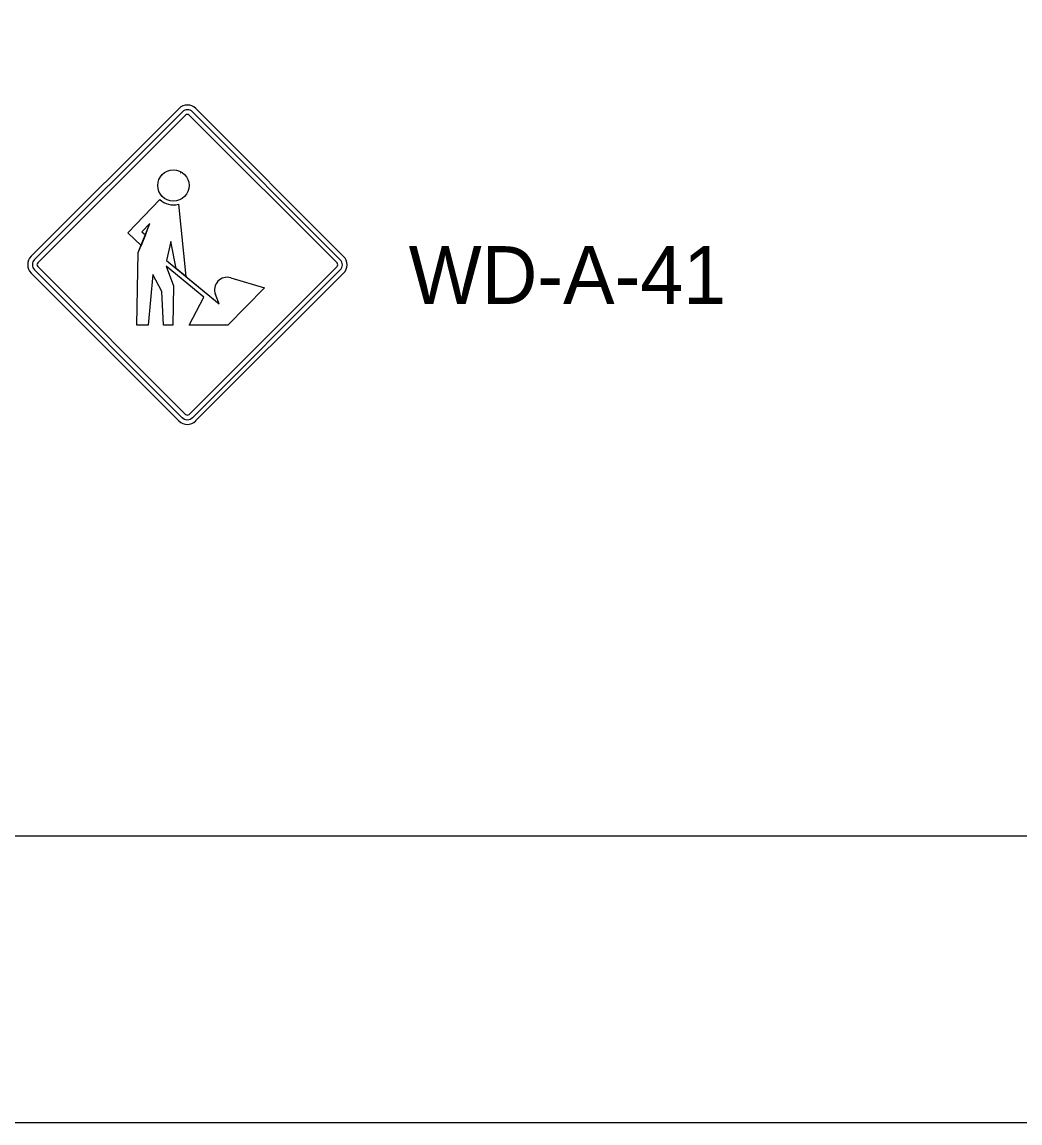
# Model space of a CAD drawing. Extents: x 2195 to 2411, y 202 to 481.
# Drawn here: x 2299.55 to 2337.18, y 201.88 to 243.38 of the extents above; entities that cross this region are included whole.
import ezdxf

# ---------------------------------------------------------------- set-up
doc = ezdxf.new("R2010")
doc.units = 0
for name, color, linetype in [('Level 1', 7, 'Continuous'), ('Level 10', 7, 'Continuous'), ('Level 60', 7, 'Continuous')]:
    doc.layers.add(name, color=color, linetype=linetype)

msp = doc.modelspace()

# ---------------------------------------------------------------- linework, layer by layer
at = {"layer": 'Level 1'}
for p, q in [((2305.47, 240.119), (2299.892, 234.546)), ((2305.594, 239.994), (2300.016, 234.422)), ((2305.718, 239.87), (2300.14, 234.299)), ((2311.427, 234.296), (2305.852, 239.87)), ((2311.55, 234.42), (2305.976, 239.993)), ((2311.674, 234.542), (2306.1, 240.117)), ((2305.525, 237.676), (2305.51, 237.676)), ((2300.016, 234.04), (2305.59, 228.465)), ((2300.14, 234.164), (2305.715, 228.59)), ((2305.849, 228.59), (2311.426, 234.161)), ((2305.973, 228.465), (2311.55, 234.036)), ((2299.892, 233.916), (2305.466, 228.341)), ((2306.096, 228.341), (2311.674, 233.912))]:
    msp.add_line(p, q, dxfattribs=at)
for points in [[(2304.063, 235.469), (2304.198, 235.356), (2304.037, 234.953), (2303.532, 235.431), (2304.748, 236.686)], [(2304.063, 235.469), (2304.198, 235.356), (2304.037, 234.953), (2303.532, 235.431), (2304.748, 236.686)], [(2304.48, 233.86), (2304.302, 231.957), (2303.875, 231.957), (2303.933, 234.69), (2304.038, 234.953), (2303.532, 235.431), (2304.748, 236.686)], [(2305.445, 236.508), (2305.727, 233.788), (2305.364, 234.087), (2305.158, 235.1), (2304.99, 234.395), (2306.976, 232.757), (2306.839, 233.111)], [(2305.445, 236.508), (2305.727, 233.788), (2305.364, 234.087), (2305.158, 235.1), (2304.99, 234.395), (2306.976, 232.757), (2306.839, 233.111)], [(2305.445, 236.508), (2305.727, 233.786), (2306.976, 232.757), (2306.839, 233.111)], [(2307.418, 233.738), (2308.698, 233.356), (2307.314, 231.957), (2305.857, 231.957), (2306.403, 233.012), (2304.989, 234.17), (2305.266, 233.432), (2305.23, 231.957), (2304.883, 231.957), (2304.82, 233.217), (2304.48, 233.86), (2304.302, 231.957), (2303.875, 231.957), (2303.933, 234.69), (2304.372, 235.786), (2304.063, 235.469)], [(2307.418, 233.738), (2308.698, 233.356), (2307.314, 231.957), (2305.857, 231.957), (2306.403, 233.012), (2304.989, 234.17), (2305.266, 233.432), (2305.23, 231.957), (2304.883, 231.957), (2304.82, 233.217), (2304.48, 233.86), (2304.302, 231.957), (2303.875, 231.957), (2303.933, 234.69), (2304.372, 235.786), (2304.063, 235.469)], [(2307.418, 233.738), (2308.698, 233.356), (2307.314, 231.957), (2305.857, 231.957), (2306.403, 233.012), (2304.989, 234.17), (2305.266, 233.432), (2305.23, 231.957), (2304.883, 231.957), (2304.82, 233.217), (2304.48, 233.86)]]:
    msp.add_lwpolyline(points, dxfattribs=at)
for points in [[(2304.063, 235.469), (2304.199, 235.356), (2304.372, 235.786)], [(2305.364, 234.085), (2305.158, 235.1), (2304.99, 234.395)]]:
    msp.add_lwpolyline(points, close=True, dxfattribs=at)
msp.add_circle((2305.256, 237.217), 0.591, dxfattribs=at)
msp.add_circle((2305.256, 237.217), 0.591, dxfattribs=at)
msp.add_circle((2305.256, 237.217), 0.591, dxfattribs=at)
for centre, radius, start, end in [((2305.785, 239.802), 0.446, 45, 134.9651), ((2305.785, 239.802), 0.27, 45, 134.9651), ((2305.785, 239.802), 0.0948, 45, 134.9651), ((2305.256, 237.217), 0.734, 226.3135, 284.9576), ((2305.256, 237.217), 0.734, 226.3135, 284.9576), ((2305.256, 237.217), 0.734, 226.3135, 284.9576), ((2300.207, 234.231), 0.446, 134.965, 225), ((2311.36, 234.228), 0.446, 314.9651, 45), ((2300.207, 234.231), 0.27, 134.965, 225), ((2300.207, 234.231), 0.0948, 134.965, 225), ((2311.36, 234.228), 0.0948, 314.9651, 45), ((2311.36, 234.228), 0.27, 314.9651, 45), ((2307.282, 233.282), 0.475, 73.381, 201.0999), ((2307.282, 233.282), 0.475, 73.381, 201.0999), ((2307.282, 233.282), 0.475, 73.381, 201.0999), ((2305.782, 228.657), 0.446, 225, 314.9652), ((2305.782, 228.657), 0.27, 225, 314.9652), ((2305.782, 228.657), 0.0948, 225, 314.9652)]:
    msp.add_arc(centre, radius, start, end, dxfattribs=at)
at = {"layer": 'Level 60'}
for points in [[(2195.401, 480.884), (2411.401, 480.884), (2411.401, 201.884), (2195.401, 201.884)], [(2214.527, 470.075), (2401.401, 470.075), (2401.401, 212.693), (2214.527, 212.693)]]:
    msp.add_lwpolyline(points, close=True, dxfattribs=at)

# ---------------------------------------------------------------- texts
at = {"layer": 'Level 10'}
msp.add_text('WD-A-41', height=2.1774, rotation=360, dxfattribs=at).set_placement((2314.131, 232.752))

doc.saveas('drawing.dxf')
